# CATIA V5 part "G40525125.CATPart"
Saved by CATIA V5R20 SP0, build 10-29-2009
Part number: G40525125
Revision: 10
Definition: design
Nomenclature: G40525125
Source: made
Description: NOT SPECIFIED
Bounding box of the stored display mesh (mm): x -62.5 to 62.5, y -30 to 0, z -12.5 to 12.5
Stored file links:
  C:\Users\Raffaele\Desktop\3D X SITO CF\BOLEX\29-GUIDE STRIP REF 405\G40525125.CATPart
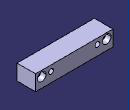
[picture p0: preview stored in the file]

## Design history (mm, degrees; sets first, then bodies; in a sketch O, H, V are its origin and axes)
Body1 "MANIFOLD_SOLID_BREP #3622" (main body)
  Solid1: solid without history
Body2 "MANIFOLD_SOLID_BREP #3760"
  Solid2: solid without history
Body3 "MANIFOLD_SOLID_BREP #3872"
  Solid3: solid without history
Body4 "MANIFOLD_SOLID_BREP #3984"
  Solid4: solid without history
Body5 "MANIFOLD_SOLID_BREP #4096"
  Solid5: solid without history
Body6 "MANIFOLD_SOLID_BREP #4208"
  Solid6: solid without history
Body7 "MANIFOLD_SOLID_BREP #4320"
  Solid7: solid without history
Body8 "MANIFOLD_SOLID_BREP #4432"
  Solid8: solid without history
Body9 "MANIFOLD_SOLID_BREP #4544"
  Solid9: solid without history
Body10 "MANIFOLD_SOLID_BREP #4656"
  Solid10: solid without history
Body11 "MANIFOLD_SOLID_BREP #4768"
  Solid11: solid without history
Body12 "MANIFOLD_SOLID_BREP #4880"
  Solid12: solid without history
Body13 "MANIFOLD_SOLID_BREP #5018"
  Solid13: solid without history
Body14 "MANIFOLD_SOLID_BREP #5156"
  Solid14: solid without history
Body15 "MANIFOLD_SOLID_BREP #5294"
  Solid15: solid without history
Body16 "MANIFOLD_SOLID_BREP #5432"
  Solid16: solid without history
Body17 "MANIFOLD_SOLID_BREP #5570"
  Solid17: solid without history
Body18 "MANIFOLD_SOLID_BREP #5708"
  Solid18: solid without history
Body19 "MANIFOLD_SOLID_BREP #5846"
  Solid19: solid without history
Body20 "MANIFOLD_SOLID_BREP #5984"
  Solid20: solid without history
Body21 "MANIFOLD_SOLID_BREP #6096"
  Solid21: solid without history
Body22 "MANIFOLD_SOLID_BREP #6208"
  Solid22: solid without history
Body23 "MANIFOLD_SOLID_BREP #6320"
  Solid23: solid without history
Body24 "MANIFOLD_SOLID_BREP #6432"
  Solid24: solid without history
Body25 "MANIFOLD_SOLID_BREP #6544"
  Solid25: solid without history
Body26 "MANIFOLD_SOLID_BREP #6656"
  Solid26: solid without history
Body27 "MANIFOLD_SOLID_BREP #6768"
  Solid27: solid without history
Body28 "MANIFOLD_SOLID_BREP #6880"
  Solid28: solid without history
Body29 "MANIFOLD_SOLID_BREP #6992"
  Solid29: solid without history
Body30 "MANIFOLD_SOLID_BREP #7104"
  Solid30: solid without history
